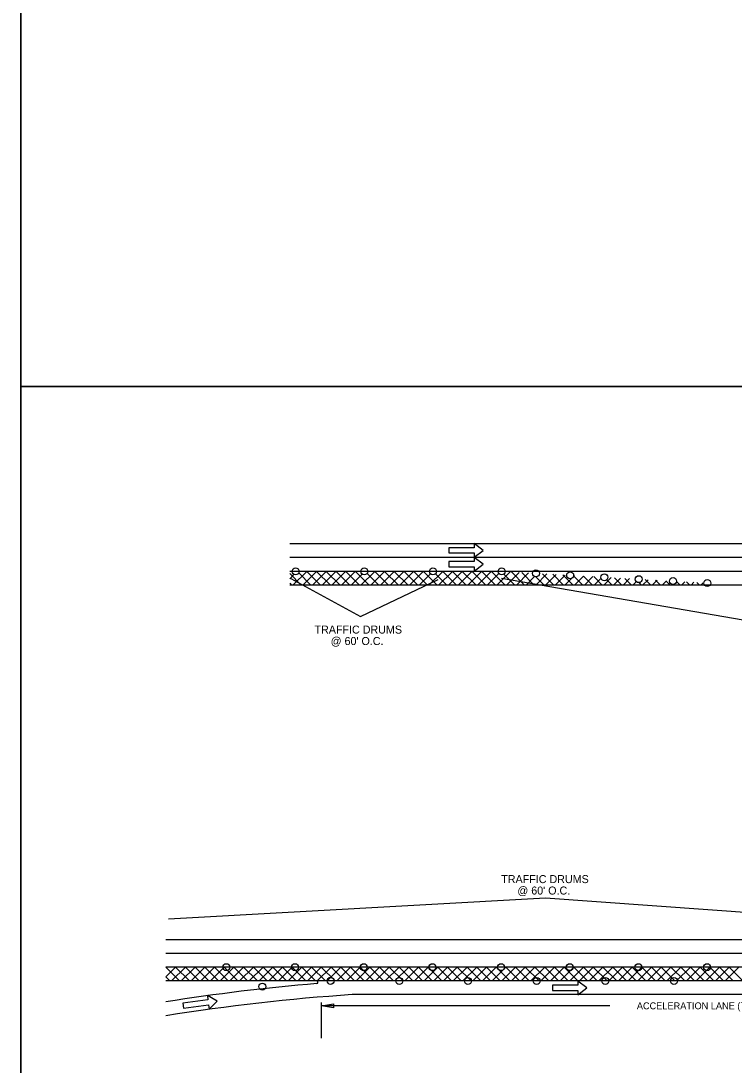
# Model space of a CAD drawing. Extents: x -100 to 745, y -1581 to -107.
# Drawn here: x 175.4 to 237.7, y -1199.9 to -1108.6 of the extents above; entities that cross this region are included whole.
import ezdxf

# ---------------------------------------------------------------- set-up
doc = ezdxf.new("R2010")
doc.units = 0
for name, color, linetype in [('Default', 7, 'Continuous'), ('R_Contour Annot', 7, 'Continuous'), ('R_Draft', 7, 'Continuous'), ('R_Drive', 7, 'Continuous'), ('R_Erosion', 7, 'Continuous'), ('R_Exist Surface', 7, 'Continuous')]:
    doc.layers.add(name, color=color, linetype=linetype)

msp = doc.modelspace()

# ---------------------------------------------------------------- linework, layer by layer
at = {"layer": 'Default'}
for points in [[(215.006, -1155.508), (215.785, -1154.908), (215.006, -1154.308), (215.006, -1154.683), (212.799, -1154.683), (212.799, -1155.133), (215.006, -1155.133)], [(215.006, -1156.716), (215.785, -1156.116), (215.006, -1155.516), (215.006, -1155.891), (212.799, -1155.891), (212.799, -1156.341), (215.006, -1156.341)], [(224.057, -1193.753), (224.835, -1193.153), (224.057, -1192.553), (224.057, -1192.928), (221.85, -1192.928), (221.85, -1193.378), (224.057, -1193.378)], [(191.855, -1195.02), (192.549, -1194.324), (191.698, -1193.831), (191.747, -1194.203), (189.559, -1194.492), (189.618, -1194.938), (191.806, -1194.649)]]:
    msp.add_lwpolyline(points, close=True, dxfattribs=at)
at = {"layer": 'R_Contour Annot'}
for points in [[(175.406, -1030.582), (345.406, -1030.582), (345.406, -1140.582), (175.406, -1140.582)], [(175.406, -1140.582), (345.406, -1140.582), (345.406, -1250.582), (175.406, -1250.582)]]:
    msp.add_lwpolyline(points, close=True, dxfattribs=at)
at = {"layer": 'R_Draft'}
for p, q in [((319.887, -1154.341), (198.887, -1154.339)), ((319.887, -1155.541), (198.887, -1155.539)), ((319.887, -1156.741), (198.887, -1156.739)), ((198.887, -1156.929), (199.896, -1157.939)), ((198.887, -1157.379), (199.255, -1157.011)), ((199.176, -1157.939), (200.376, -1156.739)), ((199.679, -1156.873), (200.745, -1157.939)), ((200.024, -1157.939), (201.224, -1156.739)), ((200.393, -1156.739), (201.593, -1157.939)), ((200.873, -1157.939), (202.073, -1156.739)), ((201.242, -1156.739), (202.442, -1157.939)), ((201.721, -1157.939), (202.921, -1156.739)), ((202.09, -1156.739), (203.29, -1157.939)), ((202.57, -1157.939), (203.77, -1156.739)), ((202.939, -1156.739), (204.139, -1157.939)), ((203.418, -1157.939), (204.618, -1156.739)), ((203.787, -1156.739), (204.987, -1157.939)), ((204.267, -1157.939), (205.218, -1156.987)), ((204.636, -1156.739), (205.836, -1157.939)), ((205.115, -1157.939), (206.315, -1156.739)), ((205.657, -1156.912), (206.684, -1157.939)), ((205.964, -1157.939), (207.164, -1156.739)), ((206.333, -1156.739), (207.533, -1157.939)), ((206.812, -1157.939), (208.012, -1156.739)), ((207.181, -1156.739), (208.381, -1157.939)), ((207.661, -1157.939), (208.861, -1156.739)), ((208.03, -1156.739), (209.23, -1157.939)), ((208.509, -1157.939), (209.709, -1156.739)), ((208.879, -1156.739), (210.079, -1157.939)), ((209.358, -1157.939), (210.558, -1156.739)), ((209.727, -1156.739), (210.927, -1157.939)), ((210.206, -1157.939), (211.186, -1156.959)), ((210.576, -1156.739), (211.776, -1157.939)), ((211.055, -1157.939), (212.255, -1156.739)), ((211.631, -1156.946), (212.624, -1157.939)), ((211.903, -1157.939), (213.103, -1156.739)), ((212.273, -1156.739), (213.473, -1157.939)), ((212.752, -1157.939), (213.952, -1156.739)), ((213.121, -1156.739), (214.321, -1157.939)), ((213.6, -1157.939), (214.8, -1156.739)), ((213.97, -1156.739), (215.17, -1157.939)), ((214.449, -1157.939), (215.649, -1156.739)), ((214.818, -1156.739), (216.018, -1157.939)), ((215.297, -1157.939), (216.497, -1156.739)), ((215.667, -1156.739), (216.867, -1157.939)), ((216.146, -1157.939), (217.158, -1156.927)), ((216.515, -1156.739), (217.716, -1157.939)), ((216.994, -1157.939), (218.148, -1156.786)), ((217.601, -1156.976), (218.564, -1157.939)), ((217.843, -1157.939), (218.951, -1156.831)), ((218.266, -1156.793), (219.413, -1157.939)), ((218.691, -1157.939), (219.754, -1156.877)), ((219.166, -1156.843), (220.261, -1157.939)), ((219.54, -1157.939), (220.283, -1157.196)), ((220.065, -1156.894), (220.092, -1156.922)), ((220.388, -1157.939), (221.36, -1156.968)), ((220.389, -1157.218), (221.11, -1157.939)), ((220.964, -1156.945), (221.958, -1157.939)), ((221.237, -1157.939), (222.163, -1157.013)), ((221.864, -1156.996), (222.807, -1157.939)), ((222.086, -1157.939), (222.966, -1157.059)), ((222.763, -1157.047), (223.655, -1157.939)), ((222.934, -1157.939), (223.508, -1157.366)), ((223.676, -1157.197), (223.769, -1157.104)), ((223.694, -1157.13), (224.504, -1157.939)), ((223.783, -1157.939), (224.572, -1157.149)), ((224.562, -1157.149), (225.352, -1157.939)), ((224.631, -1157.939), (225.375, -1157.195)), ((225.462, -1157.2), (226.201, -1157.939)), ((225.48, -1157.939), (226.092, -1157.327)), ((226.328, -1157.939), (226.982, -1157.286)), ((226.591, -1157.48), (227.05, -1157.939)), ((227.177, -1157.939), (227.785, -1157.331)), ((227.26, -1157.302), (227.898, -1157.939)), ((228.025, -1157.939), (228.588, -1157.377)), ((228.16, -1157.352), (228.747, -1157.939)), ((229.059, -1157.403), (229.078, -1157.422)), ((229.722, -1157.939), (230.194, -1157.467)), ((229.959, -1157.454), (230.444, -1157.939)), ((230.571, -1157.939), (230.997, -1157.513)), ((230.858, -1157.505), (231.292, -1157.939)), ((231.419, -1157.939), (231.8, -1157.558)), ((231.757, -1157.556), (232.141, -1157.939)), ((198.887, -1157.778), (199.047, -1157.939)), ((238.535, -1157.939), (198.887, -1157.939)), ((228.874, -1157.939), (229.171, -1157.641)), ((229.383, -1157.727), (229.595, -1157.939)), ((232.268, -1157.939), (232.317, -1157.89)), ((232.681, -1157.631), (232.989, -1157.939)), ((233.116, -1157.939), (233.406, -1157.649)), ((233.556, -1157.658), (233.838, -1157.939)), ((233.965, -1157.939), (234.209, -1157.695)), ((234.456, -1157.709), (234.686, -1157.939)), ((234.813, -1157.939), (235.012, -1157.74)), ((328.035, -1188.944), (188.076, -1188.944)), ((328.035, -1190.144), (188.076, -1190.144)), ((328.035, -1191.344), (188.076, -1191.344)), ((188.076, -1192.193), (188.925, -1191.344)), ((188.076, -1191.344), (188.076, -1191.344)), ((188.076, -1191.344), (189.276, -1192.544)), ((188.573, -1192.544), (189.773, -1191.344)), ((188.924, -1191.344), (190.125, -1192.544)), ((189.422, -1192.544), (190.622, -1191.344)), ((189.773, -1191.344), (190.973, -1192.544)), ((190.27, -1192.544), (191.47, -1191.344)), ((190.621, -1191.344), (191.822, -1192.544)), ((191.119, -1192.544), (192.319, -1191.344)), ((191.47, -1191.344), (192.67, -1192.544)), ((191.967, -1192.544), (193.168, -1191.344)), ((192.318, -1191.344), (193.519, -1192.544)), ((192.816, -1192.544), (194.016, -1191.344)), ((193.167, -1191.344), (194.367, -1192.544)), ((193.664, -1192.544), (194.865, -1191.344)), ((194.015, -1191.344), (195.216, -1192.544)), ((194.513, -1192.544), (195.713, -1191.344)), ((194.864, -1191.344), (196.064, -1192.544)), ((195.361, -1192.544), (196.562, -1191.344)), ((195.713, -1191.344), (196.913, -1192.544)), ((196.21, -1192.544), (197.41, -1191.344)), ((196.561, -1191.344), (197.761, -1192.544)), ((197.058, -1192.544), (198.259, -1191.344)), ((197.41, -1191.344), (198.61, -1192.544)), ((197.907, -1192.544), (199.107, -1191.344)), ((198.258, -1191.344), (199.458, -1192.544)), ((198.755, -1192.544), (199.956, -1191.344)), ((199.107, -1191.344), (200.307, -1192.544)), ((199.604, -1192.544), (200.804, -1191.344)), ((199.955, -1191.344), (201.155, -1192.544)), ((200.453, -1192.544), (201.653, -1191.344)), ((200.804, -1191.344), (202.004, -1192.544)), ((201.301, -1192.544), (202.501, -1191.344)), ((201.652, -1191.344), (202.853, -1192.544)), ((202.15, -1192.544), (203.35, -1191.344)), ((202.501, -1191.344), (203.701, -1192.544)), ((202.998, -1192.544), (204.198, -1191.344)), ((203.349, -1191.344), (204.55, -1192.544)), ((203.847, -1192.544), (205.047, -1191.344)), ((204.198, -1191.344), (205.398, -1192.544)), ((204.695, -1192.544), (205.895, -1191.344)), ((205.046, -1191.344), (206.247, -1192.544)), ((205.544, -1192.544), (206.744, -1191.344)), ((205.895, -1191.344), (207.095, -1192.544)), ((206.392, -1192.544), (207.592, -1191.344)), ((206.743, -1191.344), (207.944, -1192.544)), ((207.241, -1192.544), (208.441, -1191.344)), ((207.592, -1191.344), (208.792, -1192.544)), ((208.089, -1192.544), (209.29, -1191.344)), ((208.44, -1191.344), (209.641, -1192.544)), ((208.938, -1192.544), (210.138, -1191.344)), ((209.289, -1191.344), (210.489, -1192.544)), ((209.786, -1192.544), (210.987, -1191.344)), ((210.138, -1191.344), (211.338, -1192.544)), ((210.635, -1192.544), (211.835, -1191.344)), ((210.986, -1191.344), (212.186, -1192.544)), ((211.483, -1192.544), (212.684, -1191.344)), ((211.835, -1191.344), (213.035, -1192.544)), ((212.332, -1192.544), (213.532, -1191.344)), ((212.683, -1191.344), (213.883, -1192.544)), ((213.18, -1192.544), (214.381, -1191.344)), ((213.532, -1191.344), (214.732, -1192.544)), ((214.029, -1192.544), (215.229, -1191.344)), ((214.38, -1191.344), (215.58, -1192.544)), ((214.877, -1192.544), (216.078, -1191.344)), ((215.229, -1191.344), (216.429, -1192.544)), ((215.726, -1192.544), (216.926, -1191.344)), ((216.077, -1191.344), (217.277, -1192.544)), ((216.575, -1192.544), (217.775, -1191.344)), ((216.926, -1191.344), (218.126, -1192.544)), ((217.423, -1192.544), (218.623, -1191.344)), ((217.774, -1191.344), (218.975, -1192.544)), ((218.272, -1192.544), (219.472, -1191.344)), ((218.623, -1191.344), (219.823, -1192.544)), ((219.12, -1192.544), (220.32, -1191.344)), ((219.471, -1191.344), (220.672, -1192.544)), ((219.969, -1192.544), (221.169, -1191.344)), ((220.32, -1191.344), (221.52, -1192.544)), ((220.817, -1192.544), (222.017, -1191.344)), ((221.168, -1191.344), (222.369, -1192.544)), ((221.666, -1192.544), (222.866, -1191.344)), ((222.017, -1191.344), (223.217, -1192.544)), ((222.514, -1192.544), (223.715, -1191.344)), ((222.865, -1191.344), (224.066, -1192.544)), ((223.363, -1192.544), (224.563, -1191.344)), ((223.714, -1191.344), (224.914, -1192.544)), ((224.211, -1192.544), (225.412, -1191.344)), ((224.562, -1191.344), (225.763, -1192.544)), ((225.06, -1192.544), (226.26, -1191.344)), ((225.411, -1191.344), (226.611, -1192.544)), ((225.908, -1192.544), (227.109, -1191.344)), ((226.26, -1191.344), (227.46, -1192.544)), ((226.757, -1192.544), (227.957, -1191.344)), ((227.108, -1191.344), (228.308, -1192.544)), ((227.605, -1192.544), (228.806, -1191.344)), ((227.957, -1191.344), (229.157, -1192.544)), ((228.454, -1192.544), (229.654, -1191.344)), ((228.805, -1191.344), (230.005, -1192.544)), ((229.302, -1192.544), (230.503, -1191.344)), ((229.654, -1191.344), (230.854, -1192.544)), ((230.151, -1192.544), (231.351, -1191.344)), ((230.502, -1191.344), (231.702, -1192.544)), ((231, -1192.544), (232.2, -1191.344)), ((231.351, -1191.344), (232.551, -1192.544)), ((231.848, -1192.544), (233.048, -1191.344)), ((232.199, -1191.344), (233.4, -1192.544)), ((232.697, -1192.544), (233.897, -1191.344)), ((233.048, -1191.344), (234.248, -1192.544)), ((233.545, -1192.544), (234.745, -1191.344)), ((233.896, -1191.344), (235.097, -1192.544)), ((234.394, -1192.544), (235.594, -1191.344)), ((234.745, -1191.344), (235.945, -1192.544)), ((235.242, -1192.544), (236.442, -1191.344)), ((235.593, -1191.344), (236.794, -1192.544)), ((236.091, -1192.544), (237.291, -1191.344)), ((236.442, -1191.344), (237.642, -1192.544)), ((236.939, -1192.544), (238.14, -1191.344)), ((237.29, -1191.344), (238.491, -1192.544)), ((188.076, -1192.193), (188.428, -1192.544)), ((201.251, -1192.544), (188.076, -1192.544)), ((271.36, -1192.544), (201.251, -1192.544)), ((271.36, -1193.744), (204.347, -1193.744))]:
    msp.add_line(p, q, dxfattribs=at)
for points in [[(175.406, -1030.582), (175.406, -1140.582), (345.406, -1140.582), (345.406, -1030.582)], [(175.406, -1140.582), (175.406, -1250.582), (345.406, -1250.582), (345.406, -1140.582)]]:
    msp.add_lwpolyline(points, close=True, dxfattribs=at)
for centre, radius, start, end in [((216.384, -1372.199), 180.061, 94.81769, 99.04524), ((201.244, -1192.66), 0.116, 278.87203, 86.61393), ((216.384, -1372.199), 178.861, 93.85902, 99.10644)]:
    msp.add_arc(centre, radius, start, end, dxfattribs=at)
at = {"layer": 'R_Drive'}
for points in [[(198.987, -1157.358), (205.066, -1160.689), (211.86, -1157.462)], [(217.402, -1157.342), (250.332, -1163.025), (283.263, -1162.79)], [(268.645, -1188.728), (221.233, -1185.312), (188.295, -1187.139)]]:
    msp.add_lwpolyline(points, dxfattribs=at)
at = {"layer": 'R_Erosion'}
for centre in [(199.402, -1156.743), (205.402, -1156.743), (211.402, -1156.744), (217.402, -1156.744), (220.398, -1156.913), (223.393, -1157.083), (226.388, -1157.252), (229.383, -1157.422), (232.378, -1157.591), (235.374, -1157.761), (193.355, -1191.342), (193.355, -1191.342), (199.355, -1191.342), (199.355, -1191.342), (205.355, -1191.342), (211.355, -1191.342), (217.355, -1191.342), (223.355, -1191.342), (229.355, -1191.342), (235.355, -1191.342), (202.463, -1192.54), (208.464, -1192.542), (214.464, -1192.542), (220.464, -1192.542), (226.464, -1192.542), (232.464, -1192.542), (196.503, -1193.042)]:
    msp.add_circle(centre, 0.305, dxfattribs=at)
at = {"layer": 'R_Exist Surface'}
for p, q in [((201.667, -1197.547), (201.667, -1194.423)), ((226.856, -1194.723), (201.667, -1194.723))]:
    msp.add_line(p, q, dxfattribs=at)
msp.add_lwpolyline([(202.717, -1194.91), (201.667, -1194.723), (202.717, -1194.535)], close=True, dxfattribs=at)

# ---------------------------------------------------------------- texts
at = {"layer": 'R_Drive'}
for s, p in [('TRAFFIC DRUMS', (201.059, -1162.18)), ("@ 60' O.C.", (202.47, -1163.18)), ('TRAFFIC DRUMS ', (217.372, -1183.994)), ("@ 60' O.C.", (218.783, -1184.994))]:
    msp.add_text(s, height=0.7, rotation=360, dxfattribs=at).set_placement(p)
at = {"layer": 'R_Exist Surface'}
msp.add_text("ACCELERATION LANE (700' NORM.)", height=0.6, dxfattribs=at).set_placement((229.217, -1195.023))

doc.saveas('drawing.dxf')
